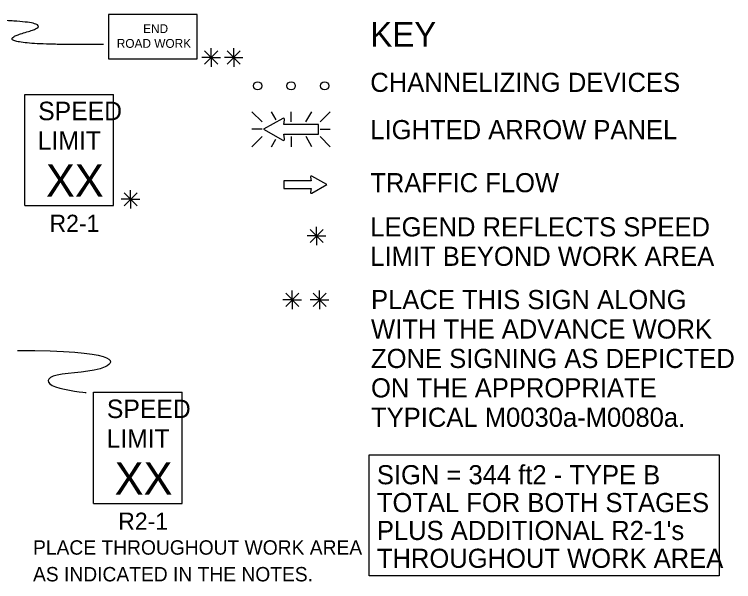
# Model space of a CAD drawing. Extents: x 16576 to 19508, y 5728 to 6974.
# Drawn here: x 17065.4 to 17415.4, y 6643.2 to 6919.1 of the extents above; entities that cross this region are included whole.
import ezdxf

# ---------------------------------------------------------------- set-up
doc = ezdxf.new("R2010")
doc.units = 0
for name, color, linetype in [('MT_SCRATCH_LEVEL_E', 7, 'Continuous'), ('TRAFFIC_SIGNS_PR', 7, 'Continuous'), ('TYPICAL_TEXT_DIMEN_EX', 7, 'Continuous'), ('TYPICAL_TEXT_DIMEN_PR', 7, 'Continuous')]:
    doc.layers.add(name, color=color, linetype=linetype)

msp = doc.modelspace()

# ---------------------------------------------------------------- linework, layer by layer
at = {"layer": 'MT_SCRATCH_LEVEL_E'}
for p, q in [((17217.37, 6836.29), (17210.13, 6840.4)), ((17209.76, 6838.14), (17196.5, 6838.14)), ((17196.5, 6838.14), (17196.5, 6834.4)), ((17209.44, 6839.92), (17209.76, 6838.14)), ((17196.5, 6834.4), (17209.76, 6834.4)), ((17209.76, 6834.4), (17209.44, 6832.62)), ((17210.13, 6832.15), (17217.37, 6836.29))]:
    msp.add_line(p, q, dxfattribs=at)
for centre, start, end in [((17209.9, 6839.99), 60.4248, 189.9638), ((17209.9, 6832.55), 170.0362, 299.7731)]:
    msp.add_arc(centre, 0.463, start, end, dxfattribs=at)
at = {"layer": 'TRAFFIC_SIGNS_PR'}
for p, q in [((17070.45, 6880.17), (17113.65, 6880.17)), ((17070.45, 6826.17), (17070.45, 6880.17)), ((17113.65, 6826.17), (17113.65, 6880.17)), ((17180.95, 6871.72), (17185.88, 6866.79)), ((17192.71, 6867.9), (17190.51, 6871.72)), ((17200.03, 6866.79), (17200.03, 6871.72)), ((17207.27, 6866.79), (17210.12, 6871.72)), ((17214.18, 6866.79), (17219.12, 6871.72)), ((17185.88, 6863.23), (17180.95, 6863.23)), ((17214.18, 6863.23), (17219.12, 6863.23)), ((17180.95, 6854.74), (17185.88, 6859.68)), ((17190.46, 6854.74), (17192.57, 6858.4)), ((17200.03, 6859.68), (17200.03, 6854.74)), ((17210.16, 6854.74), (17207.31, 6859.68)), ((17214.18, 6859.68), (17219.12, 6854.74)), ((17070.45, 6826.17), (17113.65, 6826.17)), ((17103.89, 6735.29), (17147.09, 6735.29)), ((17103.89, 6681.29), (17103.89, 6735.29)), ((17147.09, 6681.29), (17147.09, 6735.29)), ((17103.89, 6681.29), (17147.09, 6681.29))]:
    msp.add_line(p, q, dxfattribs=at)
msp.add_lwpolyline([(17111.13, 6897.5), (17154.33, 6897.5), (17154.33, 6919.1), (17111.13, 6919.1)], close=True, dxfattribs=at)
for points in [[(17195.96, 6868.51), (17186.67, 6863.23), (17195.96, 6857.91)], [(17196.84, 6858.54), (17196.44, 6860.81), (17213.45, 6860.81), (17213.45, 6865.61), (17196.44, 6865.61), (17196.84, 6867.89)]]:
    msp.add_lwpolyline(points, dxfattribs=at)
for centre in [(17183.74, 6884.34), (17200.04, 6884.34), (17216.34, 6884.34)]:
    msp.add_circle(centre, 2, dxfattribs=at)
for centre, radius, start, end in [((17196.25, 6867.98), 0.598, 350.7308, 118.8916), ((17196.25, 6858.43), 0.597, 241.4833, 9.9593)]:
    msp.add_arc(centre, radius, start, end, dxfattribs=at)
msp.add_open_spline([(17108.72, 6904.51), (17046.96, 6903.75), (17094.87, 6917.06), (17025.7, 6916.51)], degree=2, dxfattribs=at)
at = {"layer": 'TYPICAL_TEXT_DIMEN_EX'}
for p, q in [((17209.25, 6814.55), (17215.63, 6808.17)), ((17215.63, 6814.55), (17209.25, 6808.17)), ((17212.44, 6811.36), (17212.44, 6815.82)), ((17212.44, 6811.36), (17207.91, 6811.36)), ((17212.44, 6811.36), (17215.63, 6811.36)), ((17212.44, 6811.36), (17216.92, 6811.36)), ((17212.44, 6811.36), (17212.44, 6806.86)), ((17200.61, 6780.3), (17200.61, 6784.75)), ((17213.93, 6780.3), (17213.93, 6784.75)), ((17197.42, 6783.48), (17203.8, 6777.11)), ((17203.8, 6783.48), (17197.42, 6777.11)), ((17217.12, 6783.48), (17210.74, 6777.11)), ((17210.75, 6783.48), (17217.12, 6777.11)), ((17200.61, 6780.3), (17196.08, 6780.3)), ((17200.61, 6780.3), (17203.8, 6780.3)), ((17200.61, 6780.3), (17205.09, 6780.3)), ((17200.61, 6780.3), (17200.61, 6775.8)), ((17213.93, 6780.3), (17209.4, 6780.3)), ((17213.93, 6780.3), (17217.12, 6780.3)), ((17213.93, 6780.3), (17218.41, 6780.3)), ((17213.93, 6780.3), (17213.93, 6775.8))]:
    msp.add_line(p, q, dxfattribs=at)
msp.add_lwpolyline([(17238.08, 6704.81), (17408.44, 6704.81), (17408.44, 6646.06), (17238.08, 6646.06)], close=True, dxfattribs=at)
at = {"layer": 'TYPICAL_TEXT_DIMEN_PR'}
for p, q in [((17157.97, 6901.35), (17164.35, 6894.97)), ((17164.35, 6901.35), (17157.97, 6894.97)), ((17161.16, 6898.16), (17161.16, 6902.62)), ((17168.94, 6901.35), (17175.32, 6894.97)), ((17175.32, 6901.35), (17168.94, 6894.97)), ((17172.13, 6898.16), (17172.13, 6902.62)), ((17161.16, 6898.16), (17156.63, 6898.16)), ((17161.16, 6898.16), (17164.35, 6898.16)), ((17161.16, 6898.16), (17165.64, 6898.16)), ((17161.16, 6898.16), (17161.16, 6893.66)), ((17172.13, 6898.16), (17167.6, 6898.16)), ((17172.13, 6898.16), (17175.32, 6898.16)), ((17172.13, 6898.16), (17176.61, 6898.16)), ((17172.13, 6898.16), (17172.13, 6893.66)), ((17121.9, 6829.2), (17121.9, 6833.66)), ((17118.72, 6832.39), (17125.09, 6826.01)), ((17125.09, 6832.39), (17118.72, 6826.01)), ((17121.9, 6829.2), (17117.37, 6829.2)), ((17121.9, 6829.2), (17125.09, 6829.2)), ((17121.9, 6829.2), (17126.38, 6829.2)), ((17121.9, 6829.2), (17121.9, 6824.7))]:
    msp.add_line(p, q, dxfattribs=at)
msp.add_open_spline([(17066.85, 6755.71), (17115.32, 6755.71), (17115.32, 6744.95), (17080.4, 6744.95), (17080.4, 6737.13), (17100.23, 6735.18), (17100.24, 6735.18)], degree=3, dxfattribs=at)

# ---------------------------------------------------------------- texts
at = {"layer": 'TRAFFIC_SIGNS_PR'}
for s, height, p in [('END', 4.31, (17128.01, 6910.02)), ('ROAD WORK', 4.31, (17115.19, 6902.84)), ('SPEED', 9, (17076.94, 6867.64)), ('LIMIT', 9, (17076.75, 6853.24)), ('XX', 15.785, (17080.7, 6830.39)), ('R2-1', 8.37, (17082.46, 6813.3)), ('SPEED', 9, (17110.38, 6722.76)), ('LIMIT', 9, (17110.2, 6708.36)), ('XX', 15.785, (17114.15, 6685.52)), ('R2-1', 8.37, (17115.9, 6668.42)), ('PLACE THROUGHOUT WORK AREA', 7, (17074.43, 6656.33)), ('AS INDICATED IN THE NOTES.', 7, (17074.43, 6643.33))]:
    msp.add_text(s, height=height, dxfattribs=at).set_placement(p)
at = {"layer": 'TYPICAL_TEXT_DIMEN_EX'}
for s, height, p in [('KEY', 12, (17238.58, 6903.45)), ('CHANNELIZING DEVICES', 9.31, (17238.58, 6881.4)), ('LIGHTED ARROW PANEL', 9.31, (17238.58, 6858.4)), ('TRAFFIC FLOW', 9.3, (17238.58, 6832.61)), ('LEGEND REFLECTS SPEED', 9.31, (17238.58, 6811.11)), ('LIMIT BEYOND WORK AREA', 9.31, (17238.58, 6796.8)), ('PLACE THIS SIGN ALONG', 9.31, (17238.94, 6775.74)), ('WITH THE ADVANCE WORK', 9.31, (17238.94, 6761.43)), ('ZONE SIGNING AS DEPICTED', 9.31, (17238.94, 6747.12)), ('ON THE APPROPRIATE', 9.31, (17238.94, 6732.81)), ('TYPICAL M0030a-M0080a.', 9.31, (17238.94, 6718.5)), ('SIGN = 344 ft2 - TYPE B', 9.3, (17241.8, 6690.57)), ('TOTAL FOR BOTH STAGES', 9.3, (17241.8, 6677.02)), ("PLUS ADDITIONAL R2-1's", 9.3, (17241.8, 6663.47)), ('THROUGHOUT WORK AREA', 9.3, (17241.8, 6649.92))]:
    msp.add_text(s, height=height, dxfattribs=at).set_placement(p)

doc.saveas('drawing.dxf')
